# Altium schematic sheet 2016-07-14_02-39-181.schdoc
size 386 x 127 mm; SheetNumber: 1; SheetTotal: 1
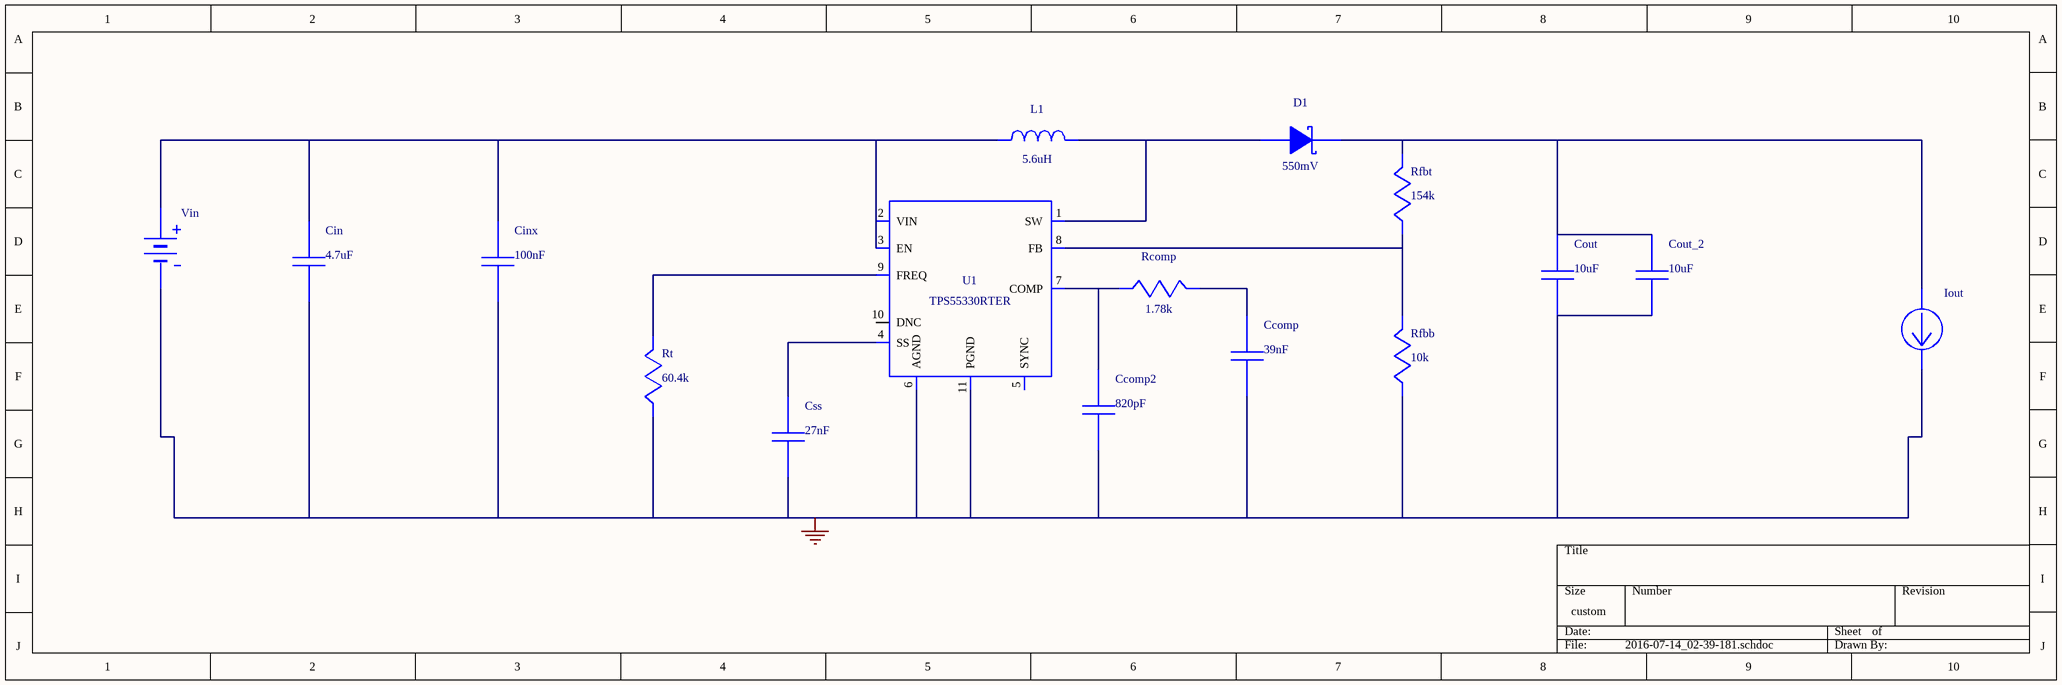
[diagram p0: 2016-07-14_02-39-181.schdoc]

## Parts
Ccomp  value 39nF  (hidden comment: GRM155R61A393KA01D)
Ccomp2  value 820pF  (hidden comment: CC0805KRX7R9BB821)
Cin  value 4.7uF  (hidden comment: GRM31CR71H475KA12L)
Cinx  value 100nF  (hidden comment: C0805C104K5RACTU)
Cout  value 10uF  (hidden comment: GRM31CR61E106KA12L)
Cout_2  value 10uF  (hidden comment: GRM31CR61E106KA12L)
Css  value 27nF  (hidden comment: GRM155R61A273KA01D)
D1  value 550mV  (hidden comment: B540C-13-F)
Iout  WB_CURRENT_LOAD  (value not drawn)
L1  value 5.6uH  (hidden comment: XAL5050-562MEB)
Rcomp  value 1.78k  (hidden comment: CRCW04021K78FKED)
Rfbb  value 10k  (hidden comment: CRCW040210K0FKED)
Rfbt  value 154k  (hidden comment: CRCW0402154KFKED)
Rt  value 60.4k  (hidden comment: CRCW040260K4FKED)
U1  TPS55330RTER
Vin  WB_BATTERY  (value not drawn)

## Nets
0: Ccomp.2 Ccomp2.1 Cin.2 Cinx.2 Cout.2 Cout_2.2 Css.2 Iout.2(-) Rfbb.2 Rt.2 U1.6(AGND) U1.11(PGND) U1.12(PGND) U1.13(PGND) U1.17(ETPAD) Vin.2(-)
NetCcomp2_2: Ccomp2.2 Rcomp.2 U1.7(COMP)
NetCcomp_1: Ccomp.1 Rcomp.1
NetCin_1: Cin.1 Cinx.1 L1.2 U1.2(VIN) U1.3(EN) Vin.1(+)
NetCout_1: Cout.1 Cout_2.1 D1.1(K) Iout.1(+) Rfbt.1
NetCss_1: Css.1 U1.4(SS)
NetD1_2: D1.2(A) L1.1 U1.1(SW) U1.15(SW) U1.16(SW)
NetRfbb_1: Rfbb.1 Rfbt.2 U1.8(FB)
NetRt_1: Rt.1 U1.9(FREQ)
NetU1_10: U1.10(DNC) U1.14(DNC)

Not connected (* = marked no-connect by the designer): U1 5(SYNC)

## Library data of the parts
Ccomp = GRM155R61A393KA01D: GRM155R61A393KA0; Manufacturer Name: MuRata
Ccomp2 = CC0805KRX7R9BB821: CC0805KRX7R9BB82; Manufacturer Name: Yageo America
Cin = GRM31CR71H475KA12L: GRM31CR71H475KA1; Manufacturer Name: MuRata
Cinx = C0805C104K5RACTU: Manufacturer Name: Kemet
Cout Cout_2 = GRM31CR61E106KA12L: GRM31CR61E106KA1; Manufacturer Name: MuRata
Css = GRM155R61A273KA01D: GRM155R61A273KA0; Manufacturer Name: MuRata
D1 = B540C-13-F: Manufacturer Name: Diodes Inc.
L1 = XAL5050-562MEB: Manufacturer Name: Coilcraft
Rcomp = CRCW04021K78FKED: Manufacturer Name: Vishay-Dale
Rfbb = CRCW040210K0FKED: Manufacturer Name: Vishay-Dale
Rfbt = CRCW0402154KFKED: Manufacturer Name: Vishay-Dale
Rt = CRCW040260K4FKED: Manufacturer Name: Vishay-Dale
U1 = TPS55330RTER: Manufacturer Name: Texas Instruments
